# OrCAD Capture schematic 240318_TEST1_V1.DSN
size A4; title: VOLTAGE CONTROLLED OSCILLATOR; rev: 1.0; note: 炔盲戎. 2024.03.18
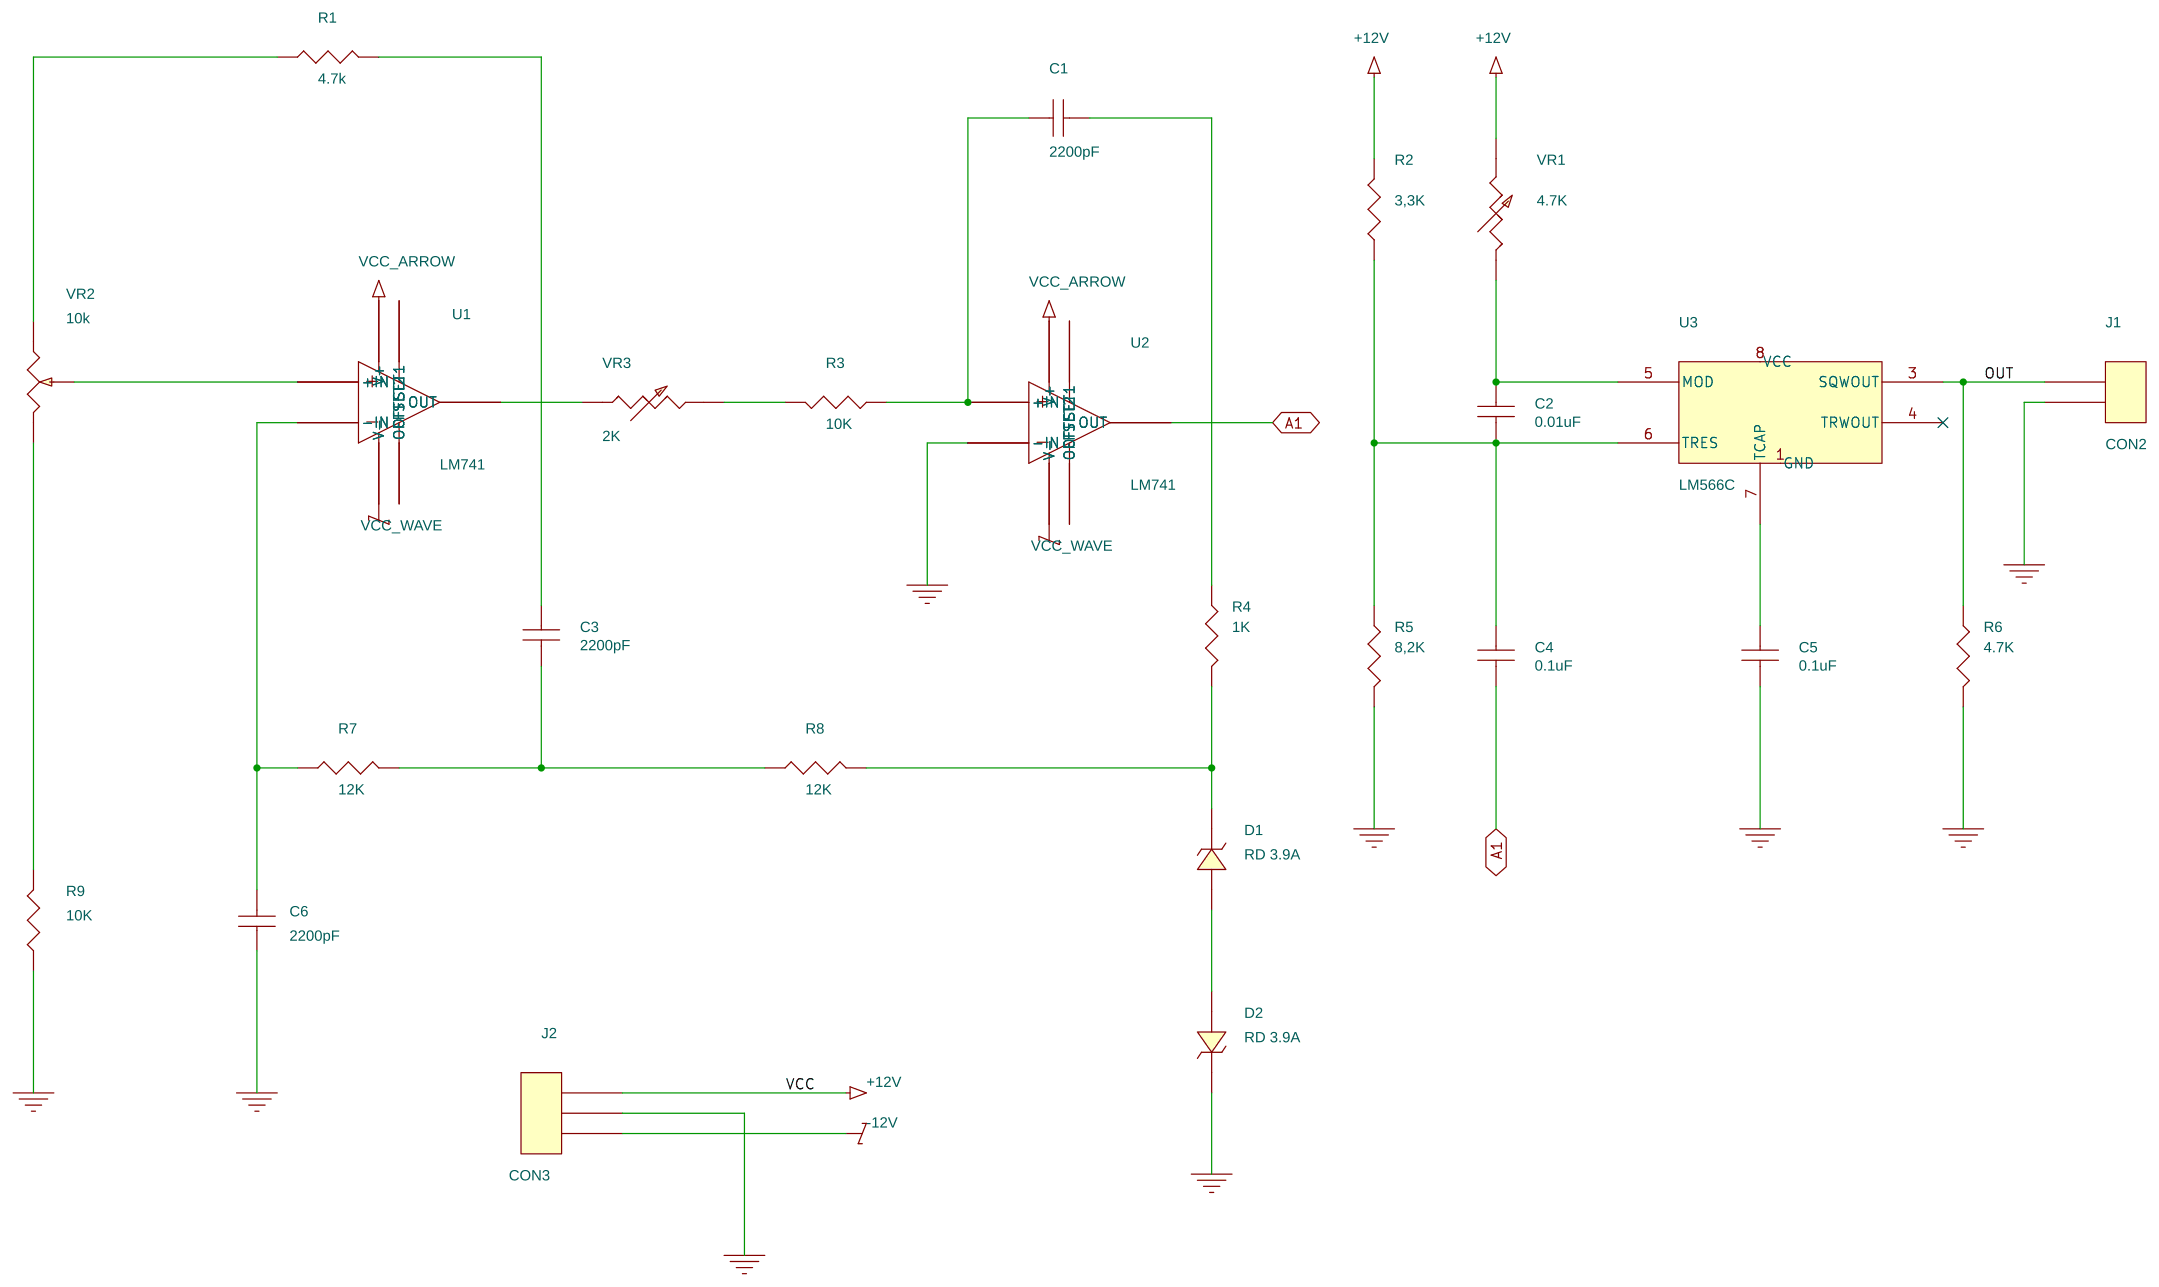
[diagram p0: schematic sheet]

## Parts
C1  2200pF
C2  0.01uF
C3  2200pF
C4  0.1uF
C5  0.1uF
C6  2200pF
D1  RD 3.9A
D2  RD 3.9A
J1  CON2
J2  CON3
R1  4.7k
R2  3,3K
R3  10K
R4  1K
R5  8,2K
R6  4.7K
R7  12K
R8  12K
R9  10K
U1  LM741
U2  LM741
U3  LM566C
VR1  4.7K
VR2  10k
VR3  2K

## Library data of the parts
C1-C6 = CAP_NP
D1 D2 = DIODE_ZENER
J1 = CON2
J2 = CON3
R1-R9 = R
U1 U2 = LM741_0
U3 = LM566C_3
VR1 VR3 = RESISTOR_VAR_2
VR2 = RESISTOR_VAR

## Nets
+12V: J2.1 R2.2 U1.7(V+) U2.7(V+) U3.8(VCC) VR1.2
-12V: J2.3 U1.4(V-) U2.4(V-)
GND: C5.2 C6.1 D2.1(CATHODE) J1.2 J2.2 R5.2 R6.2 R9.1 U2.2(-IN) U3.1(GND)
A1: C4.2 U2.6(OUT)
OUT: J1.1 R6.1 U3.3(SQWOUT)
N01144: R1.1 VR2.1(A)
N01158: U1.3(+IN) VR2.2(WIPER)
N01162: U1.6(OUT) VR3.1
N01166: C3.1 R1.2
N01173: C6.2 R7.1 U1.2(-IN)
N01186: R9.2 VR2.3(B)
N01206: C3.2 R7.2 R8.1
N01220: R3.2 VR3.2
N01242: C1.1 R3.1 U2.3(+IN)
N01254: C1.2 R4.1
N01261: D1.1(CATHODE) R4.2 R8.2
N01265: D1.2(ANODE) D2.2(ANODE)
N01354: C2.2 C4.1 R2.1 R5.1 U3.6(TRES)
N01358: C2.1 U3.5(MOD) VR1.1
N01436: C5.1 U3.7(TCAP)

Not connected (* = marked no-connect by the designer): U1 1(OFFSET1) 5(OFFSET2); U2 1(OFFSET1) 5(OFFSET2); U3 4(TRWOUT)*
